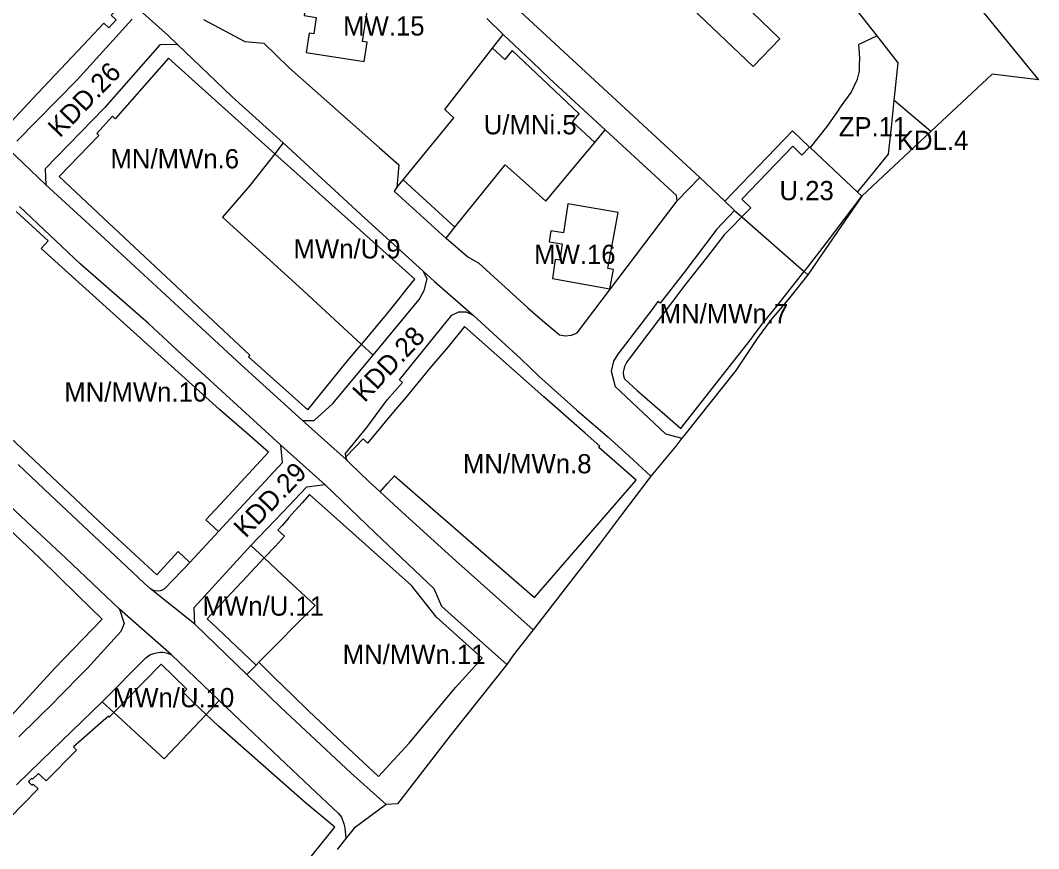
# Model space of a CAD drawing. Extents: x 7425067 to 7426806, y 5549054 to 5550619.
# Drawn here: x 7426541.6 to 7426806.4, y 5549411.9 to 5549627.2 of the extents above; entities that cross this region are included whole.
import ezdxf

# ---------------------------------------------------------------- set-up
doc = ezdxf.new("R2010")
doc.units = 0
for name, color, linetype in [('LIN_Linia Zabudowy Nieprzekraczalna', 7, 'Continuous'), ('LIN_linia zabudowy obowiązująca', 7, 'Continuous'), ('LIN_linie_rozgraniczajace', 7, 'Continuous'), ('TXT_Oznaczenia_przeznaczen', 7, 'Continuous')]:
    doc.layers.add(name, color=color, linetype=linetype)

msp = doc.modelspace()

# ---------------------------------------------------------------- linework, layer by layer
at = {"layer": 'LIN_Linia Zabudowy Nieprzekraczalna'}
for points in [[(7426538.0268, 5549599.6257), (7426544.74, 5549606.81), (7426559.36, 5549622.35), (7426563.29, 5549626.51), (7426564.58, 5549625.28), (7426566.52, 5549627.33), (7426565.24, 5549628.54), (7426567.25, 5549630.67), (7426561.59, 5549636.03), (7426548.12, 5549648.56), (7426531.28, 5549664.88), (7426518.913, 5549676.7566), (7426478.07, 5549715.98), (7426464.99, 5549727.97), (7426453.6444, 5549738.2083), (7426440.2683, 5549750.2788)], [(7426690.9454, 5549595.4765), (7426685.1665, 5549600.7989), (7426686.9556, 5549602.9223), (7426669.4544, 5549619.3642), (7426667.5724, 5549617.0033), (7426664.3654, 5549619.957)], [(7426580.1011, 5549617.3597), (7426566.2751, 5549601.6572), (7426565.56, 5549602.31), (7426561.45, 5549597.81), (7426562.0307, 5549597.273), (7426551.6857, 5549586.6071)], [(7426644.1314, 5549559.9424), (7426616.79, 5549584.46), (7426607.7603, 5549592.5571), (7426580.1011, 5549617.3597)], [(7426746.8459, 5549594.2779), (7426744.836, 5549592.1854), (7426742.49, 5549594.49), (7426729.23, 5549580.76), (7426731.5816, 5549578.4782), (7426729.1888, 5549576.1679)], [(7426551.6857, 5549586.6071), (7426563.1033, 5549575.916), (7426601.266, 5549540.1812)], [(7426641.1629, 5549585.7918), (7426648.3363, 5549579.1911), (7426654.6073, 5549573.4543)], [(7426412.8563, 5549581.6544), (7426396.03, 5549563.69), (7426404.67, 5549555.61), (7426420.91, 5549541.33), (7426423.35, 5549539.08), (7426424.73, 5549537.74), (7426431.3126, 5549531.6576), (7426439.18, 5549524.38), (7426447.81, 5549516.35), (7426457.06, 5549507.81), (7426459.86, 5549505.23), (7426466.65, 5549498.95), (7426473.46, 5549492.05), (7426482.4, 5549483.78), (7426487.2, 5549479.22), (7426492.88, 5549473.96), (7426510.35, 5549457.84), (7426515.95, 5549452.58), (7426520.98, 5549447.85), (7426523.82, 5549444.93), (7426531.3, 5549437.91), (7426537.37, 5549444.38), (7426550.43, 5549458.71), (7426562.87, 5549471.53)], [(7426746.3041, 5549562.9598), (7426751.2652, 5549569.4094), (7426760.42, 5549581.52)], [(7426606.1385, 5549514.944), (7426600.47, 5549519.88), (7426593.35, 5549526.08), (7426546.9922, 5549567.8692), (7426548.84, 5549569.88), (7426540.53, 5549577.51)], [(7426729.1888, 5549576.1679), (7426726.3682, 5549573.2143), (7426724.6335, 5549571.4262), (7426720.2853, 5549565.8424), (7426714.6734, 5549558.7055), (7426707.4296, 5549549.2129), (7426700.1679, 5549539.5902), (7426699.41, 5549538.5276), (7426699.234, 5549538.2236), (7426698.8512, 5549537.5505), (7426698.7298, 5549537.2331), (7426698.4112, 5549536.0673), (7426698.3313, 5549535.7544), (7426698.3232, 5549535.5425), (7426698.4094, 5549534.7997), (7426698.7315, 5549534.048), (7426698.8886, 5549533.8525), (7426701.9703, 5549530.975), (7426709.1576, 5549524.7072), (7426713.3132, 5549521.1023)], [(7426734.3975, 5549548.131), (7426738.2943, 5549552.8903), (7426743.1278, 5549559.0095), (7426745.4566, 5549561.9058), (7426746.3041, 5549562.9598)], [(7426629.1052, 5549541.5165), (7426630.2913, 5549542.9365), (7426636.0314, 5549549.808), (7426639.0285, 5549553.4877), (7426642.2999, 5549557.5449), (7426644.1314, 5549559.9424)], [(7426713.3132, 5549521.1023), (7426714.2267, 5549522.2628), (7426723.4513, 5549533.966), (7426731.7949, 5549544.6277), (7426731.8775, 5549544.731), (7426734.3975, 5549548.131)], [(7426657.0916, 5549547.6135), (7426652.8048, 5549542.3629), (7426648.0424, 5549536.7918), (7426641.8465, 5549529.1421), (7426638.6318, 5549525.4452)], [(7426701.7167, 5549507.7007), (7426692.04, 5549516.16), (7426692.33, 5549516.49), (7426688.45, 5549519.88), (7426677.69, 5549529.31), (7426657.0916, 5549547.6135)], [(7426510.21, 5549544.55), (7426519.55, 5549535.9), (7426531.82, 5549525.34), (7426540.51, 5549517.25), (7426563.54, 5549495.57), (7426577.1, 5549483.08), (7426582.613, 5549489.0782), (7426585.65, 5549486.27), (7426593.11, 5549494.36)], [(7426601.266, 5549540.1812), (7426600.89, 5549539.75), (7426616.3354, 5549525.989)], [(7426616.3354, 5549525.989), (7426619.2754, 5549529.6262), (7426626.2694, 5549538.1699), (7426629.1052, 5549541.5165)], [(7426638.6318, 5549525.4452), (7426631.8988, 5549517.2623)], [(7426631.8988, 5549517.2623), (7426630.7243, 5549518.401), (7426626.2425, 5549513.7458)], [(7426593.11, 5549494.36), (7426589.8458, 5549497.3688), (7426594.77, 5549502.6792), (7426606.1385, 5549514.944)], [(7426626.2425, 5549513.7458), (7426626.3641, 5549512.939), (7426627.47, 5549511.94), (7426632.17, 5549507.35), (7426635.1528, 5549504.6228), (7426637.09, 5549506.77), (7426638.8878, 5549508.7627)], [(7426638.8878, 5549508.7627), (7426646.86, 5549501.84), (7426675.2863, 5549477.1559)], [(7426546.56, 5549487.47), (7426535.59, 5549497.8), (7426528.39, 5549504.53), (7426529.67, 5549505.9)], [(7426675.2863, 5549477.1559), (7426701.7167, 5549507.7007)], [(7426643.35, 5549480.3), (7426616.7976, 5549503.9632), (7426614.86, 5549501.77), (7426611.35, 5549497.91), (7426611.43, 5549497.83), (7426609.63, 5549495.85), (7426608.5666, 5549494.6463), (7426610.26, 5549493.11)], [(7426610.26, 5549493.11), (7426607.91, 5549490.51), (7426604.9613, 5549487.4614), (7426599.24, 5549481.34), (7426592.3535, 5549473.9849)], [(7426562.87, 5549471.53), (7426556.45, 5549477.77), (7426546.56, 5549487.47)], [(7426649.81, 5549472.07), (7426643.35, 5549480.3)], [(7426592.3535, 5549473.9849), (7426590.1681, 5549471.5851), (7426592.7543, 5549469.1572), (7426602.8955, 5549459.5692), (7426603.6407, 5549460.3245), (7426607.78, 5549456.22), (7426612.34, 5549451.72), (7426616.56, 5549447.72), (7426625.55, 5549439.23)], [(7426634.76, 5549430.63), (7426642.72, 5549439.24), (7426654.79, 5549453.77), (7426661.67, 5549461.42), (7426649.81, 5549472.07)], [(7426578.2334, 5549459.8051), (7426569.97, 5549451.42), (7426565.8696, 5549447.2625), (7426564.6682, 5549446.0444), (7426564.47, 5549446.27), (7426555.42, 5549438.32), (7426556.1878, 5549437.4461), (7426548.28, 5549429.46), (7426546.95, 5549430.68), (7426546.28, 5549431.38), (7426544.7347, 5549429.8853), (7426544.5, 5549430.11), (7426543.66, 5549429.31), (7426543.8802, 5549429.0898), (7426544.54, 5549428.32), (7426544.93, 5549428.66), (7426546.18, 5549427.43), (7426531.16, 5549412.07)], [(7426623.41, 5549417.42), (7426615.68, 5549423.85), (7426593.09, 5549443.74), (7426589.8927, 5549446.7722), (7426586.7, 5549449.8), (7426584.01, 5549452.46), (7426584.84, 5549453.3), (7426578.2334, 5549459.8051)], [(7426625.55, 5549439.23), (7426634.76, 5549430.63)], [(7426559.05, 5549338.85), (7426598.94, 5549387.25), (7426602.65, 5549391.8), (7426606.54, 5549396.35), (7426611.3, 5549402.56), (7426623.41, 5549417.42)]]:
    msp.add_lwpolyline(points, dxfattribs=at)
at = {"layer": 'LIN_linia zabudowy obowiązująca'}
for points in [[(7426739.09, 5549622.43), (7426707.55, 5549652.9), (7426709.02, 5549654.42), (7426679.63, 5549682.6), (7426681.22, 5549684.26), (7426648.41, 5549716.18), (7426645.18, 5549712.98), (7426625.8, 5549731.91), (7426618.88, 5549724.83), (7426638.3, 5549705.72), (7426641.59, 5549709.06), (7426674.27, 5549677.34), (7426672.66, 5549675.68), (7426701.89, 5549647.32), (7426700.25, 5549645.63), (7426732.19, 5549615.19), (7426739.09, 5549622.43)], [(7426618.96, 5549630.88), (7426615.83, 5549631.36), (7426615.39, 5549628.48), (7426618.53, 5549628), (7426617.87, 5549623.69), (7426616.67, 5549623.88), (7426615.9, 5549618.82), (7426630.98, 5549616.53), (7426631.74, 5549621.55), (7426630.6, 5549621.72), (7426632.82, 5549636.33), (7426620.09, 5549638.27)], [(7426682.87, 5549571.97), (7426679.54, 5549572.46), (7426679.13, 5549569.64), (7426682.49, 5549569.15), (7426681.86, 5549564.85), (7426680.66, 5549565.02), (7426679.94, 5549560.1), (7426694.91, 5549557.42), (7426695.81, 5549562.43), (7426694.4, 5549562.68), (7426697.02, 5549577.29), (7426683.97, 5549579.5)], [(7426683.97, 5549579.5), (7426682.87, 5549571.97)]]:
    msp.add_lwpolyline(points, dxfattribs=at)
at = {"layer": 'LIN_linie_rozgraniczajace'}
for points in [[(7426768.7838, 5549657.8369), (7426806.41, 5549611.72)], [(7426653.31, 5549646.475), (7426718.28, 5549586.37)], [(7426764.4032, 5549623.1806), (7426745.61, 5549647.09)], [(7426572.71, 5549629.78), (7426579.98, 5549623.28)], [(7426570.6275, 5549627.4872), (7426556.37, 5549611.79)], [(7426589.18, 5549627.48), (7426599.99, 5549621.71)], [(7426667.17, 5549623.56), (7426662.87, 5549627.68)], [(7426579.98, 5549623.28), (7426582.4667, 5549620.9026), (7426596.58, 5549607.41)], [(7426651.96, 5549604.02), (7426664.3654, 5549619.957), (7426667.17, 5549623.56)], [(7426668.61, 5549622.17), (7426667.17, 5549623.56)], [(7426674.65, 5549616.45), (7426668.61, 5549622.17)], [(7426764.4032, 5549623.1806), (7426759.6215, 5549620.9454)], [(7426769.89, 5549616.2), (7426764.4032, 5549623.1806)], [(7426577.8841, 5549620.8961), (7426563.46, 5549604.49)], [(7426582.4667, 5549620.9026), (7426577.8841, 5549620.8961)], [(7426599.99, 5549621.71), (7426604.925, 5549621.25)], [(7426604.925, 5549621.25), (7426611.43, 5549614.94)], [(7426754.442, 5549604.0807), (7426757.6545, 5549608.4619), (7426759.2951, 5549611.97), (7426759.8216, 5549614.0452), (7426759.85, 5549615.6723), (7426759.9057, 5549617.2826), (7426759.795, 5549618.7091), (7426759.6215, 5549620.9454)], [(7426611.43, 5549614.94), (7426635.01, 5549594.08)], [(7426679.22, 5549612.12), (7426674.65, 5549616.45)], [(7426768.11, 5549599.44), (7426768.8456, 5549606.3663), (7426769.89, 5549616.2)], [(7426540.67, 5549595.7725), (7426556.37, 5549611.79)], [(7426693.68, 5549598.77), (7426679.22, 5549612.12)], [(7426794.33, 5549613.23), (7426779.94, 5549599.78)], [(7426806.41, 5549611.72), (7426794.33, 5549613.23)], [(7426596.58, 5549607.41), (7426609.96, 5549595.34)], [(7426776.67, 5549599.8), (7426768.8456, 5549606.3663)], [(7426563.46, 5549604.49), (7426548.0688, 5549588.6233)], [(7426653.44, 5549602.68), (7426651.96, 5549604.02)], [(7426754.442, 5549604.0807), (7426751.3288, 5549599.6267), (7426746.9691, 5549594.1622)], [(7426639.4864, 5549583.7425), (7426641.1629, 5549585.7918), (7426654.34, 5549601.9)], [(7426654.34, 5549601.9), (7426653.44, 5549602.68)], [(7426685.975, 5549589.49), (7426690.9454, 5549595.4765), (7426693.68, 5549598.77)], [(7426712.21, 5549581.69), (7426693.68, 5549598.77)], [(7426742.3714, 5549598.4814), (7426724.8059, 5549580.1895)], [(7426742.3714, 5549598.4814), (7426746.8459, 5549594.2779), (7426746.9691, 5549594.1622), (7426759.33, 5549582.55)], [(7426779.94, 5549599.78), (7426778.4049, 5549598.344), (7426760.42, 5549581.52)], [(7426767.36, 5549592.39), (7426768.11, 5549599.44)], [(7426778.4049, 5549598.344), (7426776.67, 5549599.8)], [(7426548.1702, 5549584.4192), (7426536.2854, 5549595.7734)], [(7426609.96, 5549595.34), (7426607.7603, 5549592.5571), (7426601.2257, 5549584.2898)], [(7426609.96, 5549595.34), (7426631.13, 5549575.79)], [(7426635.01, 5549594.08), (7426640.0498, 5549589.6216)], [(7426760.6, 5549584.11), (7426767.36, 5549592.39)], [(7426548.0688, 5549588.6233), (7426548.1702, 5549584.4192)], [(7426640.0498, 5549589.6216), (7426639.4864, 5549583.7425)], [(7426652.2967, 5549570.5869), (7426654.6073, 5549573.4543), (7426667.69, 5549589.69)], [(7426667.69, 5549589.69), (7426672.98, 5549584.95)], [(7426678.27, 5549580.21), (7426685.975, 5549589.49)], [(7426672.98, 5549584.95), (7426678.27, 5549580.21)], [(7426712.4402, 5549580.3003), (7426718.28, 5549586.37)], [(7426718.28, 5549586.37), (7426724.8059, 5549580.1895)], [(7426548.1702, 5549584.4192), (7426563.58, 5549570.42)], [(7426601.2257, 5549584.2898), (7426594.12, 5549576.03)], [(7426638.89, 5549583.01), (7426638.85, 5549582.68)], [(7426638.85, 5549582.68), (7426652.27, 5549570.61)], [(7426639.4864, 5549583.7425), (7426638.89, 5549583.01)], [(7426759.33, 5549582.55), (7426760.6, 5549584.11)], [(7426760.42, 5549581.52), (7426759.33, 5549582.55)], [(7426699.4, 5549563.12), (7426712.4402, 5549580.3003)], [(7426712.4402, 5549580.3003), (7426712.21, 5549581.69)], [(7426724.8059, 5549580.1895), (7426727.35, 5549577.78)], [(7426760.42, 5549581.52), (7426755.22, 5549573.94)], [(7426557.16, 5549563.9), (7426541.33, 5549578.84)], [(7426727.35, 5549577.78), (7426722.67, 5549572.83)], [(7426727.35, 5549577.78), (7426729.1888, 5549576.1679), (7426745.4566, 5549561.9058), (7426746.41, 5549561.07)], [(7426594.12, 5549576.03), (7426597.89, 5549572.68)], [(7426631.13, 5549575.79), (7426646.3252, 5549562.0196), (7426649.26, 5549559.36)], [(7426597.89, 5549572.68), (7426615.11, 5549556.95)], [(7426722.47, 5549572.61), (7426714.1, 5549561.57)], [(7426722.67, 5549572.83), (7426722.47, 5549572.61)], [(7426755.22, 5549573.94), (7426746.41, 5549561.07)], [(7426563.58, 5549570.42), (7426580.43, 5549554.84)], [(7426652.27, 5549570.61), (7426652.2967, 5549570.5869), (7426657.95, 5549565.69)], [(7426574.91, 5549548.43), (7426557.16, 5549563.9)], [(7426657.95, 5549565.69), (7426660.82, 5549564.11)], [(7426660.82, 5549564.11), (7426673.55, 5549552.46)], [(7426647.35, 5549559.97), (7426646.3252, 5549562.0196)], [(7426686.36, 5549545.94), (7426699.4, 5549563.12)], [(7426714.1, 5549561.57), (7426708, 5549553.65)], [(7426746.41, 5549561.07), (7426741.94, 5549555.51)], [(7426646.63, 5549556.97), (7426647.35, 5549559.97)], [(7426649.26, 5549559.36), (7426659.31, 5549550.57)], [(7426615.11, 5549556.95), (7426630.2913, 5549542.9365), (7426633.31, 5549540.15)], [(7426645.3205, 5549554.6153), (7426646.63, 5549556.97)], [(7426580.43, 5549554.84), (7426599.01, 5549537.65)], [(7426633.31, 5549540.15), (7426645.3205, 5549554.6153)], [(7426707.33, 5549554.12), (7426706.06, 5549552.32)], [(7426708, 5549553.65), (7426707.33, 5549554.12)], [(7426740.72, 5549553.99), (7426737.89, 5549550.65)], [(7426741.94, 5549555.51), (7426740.72, 5549553.99)], [(7426640.19, 5549533.74), (7426653.83, 5549550.53)], [(7426653.83, 5549550.53), (7426655.6, 5549551.42)], [(7426655.6, 5549551.42), (7426657.49, 5549551.4)], [(7426657.49, 5549551.4), (7426659.31, 5549550.57)], [(7426659.31, 5549550.57), (7426666.59, 5549543.89)], [(7426673.55, 5549552.46), (7426676.87, 5549549.63)], [(7426706.06, 5549552.32), (7426696.93, 5549540.39)], [(7426737.89, 5549550.65), (7426736.84, 5549549.41)], [(7426583.61, 5549540.38), (7426574.91, 5549548.43)], [(7426676.87, 5549549.63), (7426681.8, 5549545.48)], [(7426736.84, 5549549.41), (7426733.25, 5549544.46)], [(7426681.8, 5549545.48), (7426683.26, 5549545.21)], [(7426683.26, 5549545.21), (7426684.93, 5549545.4)], [(7426684.93, 5549545.4), (7426686.36, 5549545.94)], [(7426666.59, 5549543.89), (7426671.75, 5549539.17)], [(7426733.25, 5549544.46), (7426727.62, 5549536.15)], [(7426592.91, 5549531.77), (7426583.61, 5549540.38)], [(7426622.85, 5549527.64), (7426633.31, 5549540.15)], [(7426696.93, 5549540.39), (7426695.8495, 5549538.6375)], [(7426599.01, 5549537.65), (7426614.9918, 5549523.2125), (7426626.3641, 5549512.939), (7426627.47, 5549511.94)], [(7426671.75, 5549539.17), (7426676.42, 5549534.73)], [(7426695.8495, 5549538.6375), (7426695.2, 5549536.03)], [(7426676.42, 5549534.73), (7426681.375, 5549530.3)], [(7426695.2, 5549536.03), (7426696.3, 5549532)], [(7426727.62, 5549536.15), (7426714.51, 5549519.66)], [(7426611.83, 5549514.52), (7426609.344, 5549516.7866), (7426592.91, 5549531.77)], [(7426637.01, 5549528.57), (7426640.94, 5549533.07)], [(7426640.94, 5549533.07), (7426640.19, 5549533.74)], [(7426696.3, 5549532), (7426709.36, 5549519.7)], [(7426681.375, 5549530.3), (7426686.33, 5549525.87)], [(7426618.0281, 5549523.2015), (7426622.85, 5549527.64)], [(7426631.65, 5549521.39), (7426637.01, 5549528.57)], [(7426686.33, 5549525.87), (7426694.24, 5549519.03)], [(7426614.9918, 5549523.2125), (7426618.0281, 5549523.2015)], [(7426626.1197, 5549514.56), (7426631.65, 5549521.39)], [(7426694.24, 5549519.03), (7426699.875, 5549513.885)], [(7426709.36, 5549519.7), (7426713.6496, 5549518.5706)], [(7426714.51, 5549519.66), (7426713.6496, 5549518.5706), (7426712.03, 5549516.52)], [(7426609.732, 5549512.2633), (7426609.344, 5549516.7866)], [(7426712.03, 5549516.52), (7426705.51, 5549508.74)], [(7426620.85, 5549506.41), (7426611.83, 5549514.52)], [(7426626.3641, 5549512.939), (7426626.2425, 5549513.7458), (7426626.1197, 5549514.56)], [(7426699.875, 5549513.885), (7426705.51, 5549508.74)], [(7426549.35, 5549503.89), (7426541, 5549511.78)], [(7426595.17, 5549496.6), (7426609.732, 5549512.2633)], [(7426627.47, 5549511.94), (7426632.17, 5549507.35)], [(7426705.51, 5549508.74), (7426697.95, 5549498.69)], [(7426616.03, 5549505.87), (7426609.81, 5549499.35)], [(7426620.85, 5549506.41), (7426616.03, 5549505.87)], [(7426620.85, 5549506.41), (7426633.87, 5549494)], [(7426632.17, 5549507.35), (7426635.1528, 5549504.6228), (7426639.8401, 5549500.3371)], [(7426535.73, 5549503.88), (7426544.575, 5549495.645)], [(7426557.93, 5549495.78), (7426549.35, 5549503.89)], [(7426639.8401, 5549500.3371), (7426654.85, 5549486.69)], [(7426609.81, 5549499.35), (7426601.53, 5549490.67)], [(7426697.95, 5549498.69), (7426692.47, 5549491.4)], [(7426544.575, 5549495.645), (7426553.42, 5549487.41)], [(7426567.71, 5549486.6), (7426557.93, 5549495.78)], [(7426593.11, 5549494.36), (7426595.17, 5549496.6)], [(7426585.65, 5549486.27), (7426593.11, 5549494.36)], [(7426633.87, 5549494), (7426649.08, 5549479.51)], [(7426601.53, 5549490.67), (7426586.7952, 5549474.5549)], [(7426601.53, 5549490.67), (7426604.9613, 5549487.4614), (7426609.875, 5549482.87)], [(7426692.47, 5549491.4), (7426674.94, 5549468.73)], [(7426553.42, 5549487.41), (7426567.3932, 5549474.156)], [(7426573.8656, 5549480.822), (7426567.71, 5549486.6)], [(7426579.12, 5549479.49), (7426585.65, 5549486.27)], [(7426654.85, 5549486.69), (7426674.94, 5549468.73)], [(7426609.875, 5549482.87), (7426618.22, 5549475.07)], [(7426575.46, 5549479.37), (7426573.8656, 5549480.822)], [(7426586.9279, 5549470.2543), (7426575.46, 5549479.37)], [(7426575.46, 5549479.37), (7426576.24, 5549479.03)], [(7426576.24, 5549479.03), (7426577.12, 5549478.92)], [(7426577.12, 5549478.92), (7426578.01, 5549478.98)], [(7426578.01, 5549478.98), (7426578.53, 5549479.15)], [(7426578.53, 5549479.15), (7426579.12, 5549479.49)], [(7426649.08, 5549479.51), (7426651.07, 5549474.89)], [(7426580.8558, 5549462.2251), (7426567.3932, 5549474.156)], [(7426567.3932, 5549474.156), (7426568.55, 5549470.36)], [(7426586.9279, 5549470.2543), (7426586.7952, 5549474.5549)], [(7426600.4942, 5549457.1421), (7426602.8955, 5549459.5692), (7426603.6407, 5549460.3245), (7426618.22, 5549475.07)], [(7426651.07, 5549474.89), (7426657.89, 5549468.83)], [(7426567.74, 5549468.32), (7426559.02, 5549458.77)], [(7426568.55, 5549470.36), (7426567.74, 5549468.32)], [(7426609.27, 5549448.66), (7426600.4942, 5549457.1421), (7426586.9279, 5549470.2543)], [(7426657.89, 5549468.83), (7426668.09, 5549459.77)], [(7426674.94, 5549468.73), (7426669.8, 5549462.24)], [(7426577.38, 5549462.87), (7426578.02, 5549462.92)], [(7426578.02, 5549462.92), (7426578.67, 5549462.91)], [(7426562.83, 5549450.05), (7426574.2, 5549461.49)], [(7426574.2, 5549461.49), (7426575.24, 5549462.21)], [(7426575.24, 5549462.21), (7426576.33, 5549462.64)], [(7426576.33, 5549462.64), (7426576.99, 5549462.8)], [(7426576.99, 5549462.8), (7426577.38, 5549462.87)], [(7426578.67, 5549462.91), (7426579.19, 5549462.83)], [(7426579.19, 5549462.83), (7426579.83, 5549462.66)], [(7426579.83, 5549462.66), (7426580.48, 5549462.42)], [(7426580.48, 5549462.42), (7426580.8558, 5549462.2251)], [(7426580.8558, 5549462.2251), (7426593.31, 5549450.39)], [(7426669.8, 5549462.24), (7426668.09, 5549459.77)], [(7426559.02, 5549458.77), (7426550.79, 5549450.42)], [(7426668.09, 5549459.77), (7426653.52, 5549441.42)], [(7426550.6878, 5549450.3164), (7426541.215, 5549440.905)], [(7426547.1, 5549434.74), (7426562.83, 5549450.05)], [(7426550.79, 5549450.42), (7426550.6878, 5549450.3164)], [(7426562.83, 5549450.05), (7426565.8696, 5549447.2625), (7426578.99, 5549435.23)], [(7426578.99, 5549435.23), (7426589.8927, 5549446.7722), (7426593.31, 5549450.39)], [(7426593.31, 5549450.39), (7426602.32, 5549441.82)], [(7426627.63, 5549431.52), (7426609.27, 5549448.66)], [(7426602.32, 5549441.82), (7426615.51, 5549429.28)], [(7426653.52, 5549441.42), (7426639.64, 5549423.47)], [(7426540.59, 5549428.41), (7426547.1, 5549434.74)], [(7426636.75, 5549423.35), (7426627.63, 5549431.52)], [(7426615.51, 5549429.28), (7426624.2911, 5549421.0303)], [(7426636.75, 5549423.35), (7426628.4, 5549417.17)], [(7426638.195, 5549423.41), (7426636.75, 5549423.35)], [(7426639.64, 5549423.47), (7426638.195, 5549423.41)], [(7426624.2911, 5549421.0303), (7426625.09, 5549420.04)], [(7426625.09, 5549420.04), (7426625.73, 5549418.35)], [(7426625.73, 5549418.35), (7426626.01, 5549417.31)], [(7426626.01, 5549417.31), (7426626.2246, 5549414.4685)], [(7426628.4, 5549417.17), (7426626.2246, 5549414.4685)], [(7426626.2246, 5549414.4685), (7426623.958, 5549411.6537)]]:
    msp.add_lwpolyline(points, dxfattribs=at)

# ---------------------------------------------------------------- texts
at = {"layer": 'TXT_Oznaczenia_przeznaczen'}
for s, p in [('MW.15', (7426625.5283, 5549623.2646)), ('U/MNi.5', (7426662.1061, 5549597.5838)), ('ZP.11', (7426754.4138, 5549597.0623)), ('KDL.4', (7426769.5283, 5549593.5446)), ('MN/MWn.6', (7426565.0244, 5549588.7405)), ('U.23', (7426739.0036, 5549580.4592)), ('MWn/U.9', (7426612.6249, 5549565.3163)), ('MW.16', (7426675.206, 5549563.8826)), ('MN/MWn.7', (7426707.8478, 5549548.4603)), ('MN/MWn.10', (7426553.0095, 5549528.0956)), ('MN/MWn.8', (7426656.6947, 5549509.4398)), ('MWn/U.11', (7426588.9751, 5549472.4263)), ('MN/MWn.11', (7426625.4197, 5549459.8808)), ('MWn/U.10', (7426565.6277, 5549448.6217))]:
    msp.add_text(s, height=5, dxfattribs=at).set_placement(p)
for s, rotation, p in [('KDD.26', 46.068083, (7426551.8419, 5549596.4918)), ('KDD.28', 46.783583, (7426631.1284, 5549527.652)), ('KDD.29', 46.068083, (7426600.1647, 5549492.4197))]:
    msp.add_text(s, height=5, rotation=rotation, dxfattribs=at).set_placement(p)

doc.saveas('drawing.dxf')
